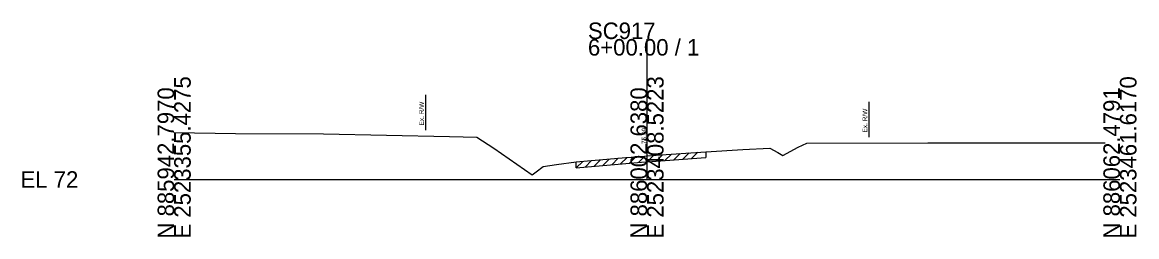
# Model space of a CAD drawing. Extents: x -26 to 218, y -10 to 12021.
# Drawn here: x -25.7 to 162.8, y 5990.3 to 6026.6 of the extents above; entities that cross this region are included whole.
import ezdxf

# ---------------------------------------------------------------- set-up
doc = ezdxf.new("R2010")
doc.units = 0
for name, color, linetype in [('RD_GPK_XS_Cell', 7, 'Continuous'), ('RD_XS_ExGround', 7, 'Continuous'), ('RD_XS_ExPaveRet', 7, 'Continuous'), ('RD_XS_ExRW', 7, 'Continuous'), ('RD_XS_TX_Elev_EX', 7, 'Continuous')]:
    doc.layers.add(name, color=color, linetype=linetype)

msp = doc.modelspace()

# ---------------------------------------------------------------- linework, layer by layer
at = {"layer": 'RD_GPK_XS_Cell'}
for p, q in [((80, 6000), (80, 6023.78)), ((0, 6000), (80, 6000)), ((80, 6000), (160, 6000))]:
    msp.add_line(p, q, dxfattribs=at)
at = {"layer": 'RD_XS_ExGround'}
for p, q in [((0, 6007.93), (10.39, 6007.81)), ((10.39, 6007.81), (25.28, 6007.72)), ((25.28, 6007.72), (46.58, 6007.26)), ((46.58, 6007.26), (51.21, 6007.19)), ((51.21, 6007.19), (54.1, 6005.28)), ((54.1, 6005.28), (60.57, 6000.78)), ((89.92, 6004.71), (96.2, 6005.06)), ((96.2, 6005.06), (100.8, 6005.29)), ((100.8, 6005.29), (102.14, 6004.55)), ((102.95, 6004.08), (105.59, 6005.45)), ((105.59, 6005.45), (107.03, 6006.16)), ((107.03, 6006.16), (127.5, 6006.18)), ((127.5, 6006.18), (136.38, 6006.18)), ((136.38, 6006.18), (157.5, 6006.19)), ((64.67, 6002.51), (68.03, 6002.98)), ((68.03, 6002.98), (76.39, 6003.7)), ((76.39, 6003.7), (79.04, 6003.92)), ((79.04, 6003.92), (80, 6003.99)), ((80, 6003.99), (81.56, 6004.1)), ((81.56, 6004.1), (89.92, 6004.71)), ((102.14, 6004.55), (102.95, 6004.08)), ((60.57, 6000.78), (61.23, 6001.28)), ((61.23, 6001.28), (62.41, 6002.21)), ((62.41, 6002.21), (64.67, 6002.51))]:
    msp.add_line(p, q, dxfattribs=at)
at = {"layer": 'RD_XS_ExPaveRet'}
for p, q in [((68.03, 6001.98), (69.12, 6003.07)), ((68.03, 6001.98), (68.03, 6002.98)), ((69.53, 6002.11), (70.62, 6003.2)), ((71.03, 6002.24), (72.12, 6003.33)), ((72.53, 6002.37), (73.62, 6003.46)), ((74.03, 6002.5), (75.12, 6003.59)), ((75.53, 6002.63), (76.62, 6003.72)), ((76.39, 6002.7), (79.04, 6002.92)), ((77.03, 6002.75), (78.12, 6003.84)), ((78.53, 6002.88), (79.61, 6003.96)), ((79.04, 6002.92), (80, 6002.99)), ((80, 6002.99), (81.56, 6003.1)), ((80.03, 6002.99), (81.1, 6004.06)), ((81.53, 6003.09), (82.61, 6004.17)), ((81.56, 6003.1), (89.92, 6003.71)), ((83.03, 6003.2), (84.11, 6004.28)), ((84.53, 6003.31), (85.61, 6004.39)), ((86.03, 6003.42), (87.11, 6004.5)), ((87.53, 6003.54), (88.61, 6004.62)), ((89.92, 6004.71), (89.92, 6003.71)), ((68.03, 6001.98), (76.39, 6002.7))]:
    msp.add_line(p, q, dxfattribs=at)
at = {"layer": 'RD_XS_ExRW'}
for p, q in [((42.5, 6014.35), (42.5, 6008.35)), ((117.5, 6013.17), (117.5, 6007.17))]:
    msp.add_line(p, q, dxfattribs=at)

# ---------------------------------------------------------------- texts
at = {"layer": 'RD_GPK_XS_Cell'}
for s, p in [('SC917', (70, 6023.78)), ('6+00.00 / 1', (70, 6020.98)), ('EL 72', (-26, 5998.6))]:
    msp.add_text(s, height=2.8, dxfattribs=at).set_placement(p)
for s, p in [('E 2523355.4275', (2.8, 5990)), ('E 2523408.5223', (82.8, 5990)), ('E 2523461.6170', (162.8, 5990)), ('N 885942.7970', (0, 5990)), ('N 886002.6380', (80, 5990)), ('N 886062.4791', (160, 5990))]:
    msp.add_text(s, height=2.8, rotation=90, dxfattribs=at).set_placement(p)
at = {"layer": 'RD_XS_ExRW'}
for p in [(42.25, 6009.13), (117.25, 6007.95)]:
    msp.add_text('Ex. R/W ', height=0.8, rotation=90, dxfattribs=at).set_placement(p)
at = {"layer": 'RD_XS_TX_Elev_EX'}
msp.add_text('75.99', height=0.8, rotation=90, dxfattribs=at).set_placement((79.9, 6005.99))

doc.saveas('drawing.dxf')
